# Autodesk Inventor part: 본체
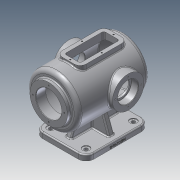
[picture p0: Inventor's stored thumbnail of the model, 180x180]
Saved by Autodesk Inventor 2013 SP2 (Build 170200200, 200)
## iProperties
Created: 2021-11
Part Number: 본체
Material: 알루미늄 6061
Document SubType Name: Modeling
Designer: aa
Density: 2.71 g/cm^3
Mass: 3552.31 g
Surface Area: 2411.25 cm^2
Volume: 1310.81 cm^3
Author: aa
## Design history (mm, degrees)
sketch "스케치1"
  geometry: L1 (0, 0)-(210, 0); L2 (0, 0)-(0, 47.5); L3 (0, 47.5)-(10, 47.5); L4 (10, 47.5)-(10, 65); L5 (10, 65)-(185.993, 65); A1 r 100 centre (110, 0) between (210, 0) and (185.993, 65); 1 further point
  constraints: 10 end point, 2 parallel, 2 perpendicular, 2 point on circle, 1 centre point, 1 coincident, 1 horizontal, 1 horizontal alignment
  dimensions: "d0" = 210 distance of L1.end L1.start; "d1" = 100 radius of A1; "d2" = 95 diameter of L3 L1; "d3" = 130 diameter of L5 L1; "d4" = 10 distance of L2.end L3.end
revolve "회전1" sketch "스케치1" stored, may be unused: angle "d8" = 90 deg
feature "쉘1" dims "d9" = 10
sketch "스케치16"
  geometry: C1 r 55 at (0, 0) reference; C2 r 37.5 at (0, 0) reference; C3 r 55 at (0, 0); C4 r 32.5 at (0, 0)
  constraints: 2 centre point, 2 coincident, 1 concentric
  dimensions: "d121" = 65 diameter of C4
extrude "돌출9" join sketch "스케치16" distance "d122" = 5; taper "d123" = 0 deg
sketch "스케치17"
  geometry: C1 r 32.5 at (0, 0) reference; C2 r 37.5 at (0, 0) reference; C3 r 32.5 at (0, 0)
  constraints: 1 centre point, 1 coincident
  dimensions: "d124" = 65 diameter of C3
extrude "돌출10" join sketch "스케치17" distance "d125" = 20; taper "d126" = 0 deg
node "작업 평면1"
sketch "스케치2"
  geometry: L1 (0, 47.5)-(0, -47.5) reference; L2 (-50, -30)-(-170, -30); L3 (-170, -30)-(-170, 30); L4 (-170, 30)-(-50, 30); L5 (-50, 30)-(-50, -30); 3 further points
  constraints: 8 end point, 2 midpoint, 2 parallel, 1 horizontal, 1 horizontal alignment, 1 perpendicular
  dimensions: "d11" = 120 distance of L3.end L4.end; "d12" = 60 distance of L2.end L3.end; "d13" = 50 distance of point (-50, 0) point (0, 0)
extrude "돌출1" join sketch "스케치2" stored distance "d14" = 25; taper "d15" = 0 deg
fillet "모깎기1" dims "d16" = 15
sketch "스케치3"
  geometry: L1 (65, 30)-(155, 30) reference; L2 (50, -15)-(50, 15) reference; L3 (155, -30)-(65, -30) reference; L4 (170, 15)-(170, -15) reference; L5 (160, 15)-(160, -15); L6 (155, -20)-(65, -20); L7 (60, -15)-(60, 15); L8 (65, 20)-(155, 20); A1 r 15 centre (155, 15) between (170, 15) and (155, 30) reference; A2 r 15 centre (65, 15) between (65, 30) and (50, 15) reference; A3 r 15 centre (65, -15) between (50, -15) and (65, -30) reference; A4 r 15 centre (155, -15) between (155, -30) and (170, -15) reference; A5 r 5 centre (155, 15) between (160, 15) and (155, 20); A6 r 5 centre (155, -15) between (155, -20) and (160, -15); A7 r 5 centre (65, -15) between (60, -15) and (65, -20); A8 r 5 centre (65, 15) between (65, 20) and (60, 15); 1 further point
  constraints: 8 end point, 8 point on circle, 4 centre point, 7 other
  dimensions: "d17" = 10 distance between parallel lines of L1 L8
extrude "돌출2" cut sketch "스케치3" stored distance "d18" = 25; taper "d19" = 0 deg
sketch "스케치4"
  geometry: L1 (65, 30)-(155, 30) reference; L2 (170, 15)-(170, -15) reference; L3 (55, 0)-(165, 0); L4 (110, 25)-(110, -25); 5 further points
  constraints: 5 midpoint, 4 end point, 3 vertical alignment, 2 horizontal alignment, 2 perpendicular
  dimensions: "d20" = 50 distance of L4.start L4.end; "d22" = 110 distance of L3.end L3.start
hole "구멍1" sketch "스케치4" at (55, 0), (110, 25), (110, -25), (165, 0) diameter "d23" = 3.242; stored, may be unused: countersink angle "d27" = 90 deg, drill point angle "d29" = 118 deg; dims "d24" = 9, "d25" = 4, "d26" = 2, "d28" = 11
node "작업 평면2"
sketch "스케치5"
  geometry: L1 (0, -47.5)-(0, 47.5) reference; L2 (0, 0)-(127, 0); C1 r 40 at (127, 0)
  constraints: 2 end point, 1 centre point, 1 coincident, 1 perpendicular
  dimensions: "d31" = 127 distance of L2.start L2.end; "d32" = 80 diameter of C1
extrude "돌출3" join sketch "스케치5" stored distance "d33" = 25; taper "d34" = 0 deg
sketch "스케치6"
  geometry: C1 r 40 at (0, 0) reference; 2 further points
  constraints: 1 coincident
hole "구멍2" sketch "스케치6" at (0, 0) diameter "d35" = 42; stored, may be unused: countersink angle "d39" = 90 deg, drill point angle "d41" = 118 deg; dims "d36" = 9, "d37" = 52, "d38" = 18, "d40" = 75
fillet "모깎기2" dims "d42" = 0.3
sketch "스케치7"
  geometry: C1 r 26 at (0, 0) reference; 5 further points
  constraints: 2 horizontal alignment, 2 vertical alignment
  dimensions: "d44" = 32.5 distance of C1.centre point (0, 32.5); "d45" = 32.5 distance of point (-32.5, 0) C1.centre; "d46" = 32.5 distance of C1.centre point (0, -32.5); "d47" = 32.5 distance of C1.centre point (32.5, 0)
hole "구멍3" sketch "스케치7" at (0, 32.5), (32.5, 0), (-32.5, 0), (0, -32.5) diameter "d48" = 3.242; stored, may be unused: countersink angle "d52" = 90 deg, drill point angle "d54" = 118 deg; dims "d49" = 11, "d50" = 52, "d51" = 18, "d53" = 13
sketch "스케치8"
  geometry: L1 (0, 0)-(0, 40); C1 r 47.5 at (0, 0) reference; 1 further point
  constraints: 2 end point, 1 coincident, 1 vertical
  dimensions: "d55" = 40 distance of L1.start L1.end
hole "구멍4" sketch "스케치8" at (0, 40) diameter "d56" = 3.242; stored, may be unused: countersink angle "d60" = 90 deg, drill point angle "d62" = 118 deg; dims "d57" = 11, "d58" = 52, "d59" = 18, "d61" = 13
node "작업 평면3"
sketch "스케치9"
  geometry: L1 (0, 47.5)-(0, -47.5) reference; L2 (0, 0)-(-30, 0); L3 (-30, -65)-(-190, -65); L4 (-190, -65)-(-190, 65); L5 (-190, 65)-(-30, 65); L6 (-30, 65)-(-30, -65)
  constraints: 10 end point, 2 parallel, 2 perpendicular, 1 horizontal, 1 midpoint
  dimensions: "d67" = 30 distance of L2.end L2.start; "d68" = 160 distance of L4.end L5.end; "d69" = 130 distance of L3.end L4.end
extrude "돌출4" join sketch "스케치9" distance "d70" = 14; taper "d71" = 0 deg
fillet "모깎기3" dims "d72" = 20
node "작업 평면4"
sketch "스케치14"
  geometry: L1 (170, -100)-(50, -100) reference; L2 (30, -100)-(50, -100) reference; L3 (170, -100)-(190, -100) reference; L4 (25, -55)-(181.239, -55) reference; L5 (50, -100)-(63.681, -62.412); L6 (10, -65)-(185.993, -65) reference; L7 (50, -100)-(170, -100); L8 (170, -100)-(156.319, -62.412); L9 (170, -100)-(210, -100); L10 (156.319, -62.412)-(63.681, -62.412); 1 further point
  constraints: 10 end point, 2 point on line, 1 equal length, 1 horizontal
  dimensions: "d98" = 110 deg angle of L2 L5; "d101" = 20 distance of L5.start L2.start; "d102" = 120 distance of L5.start L7.end; "d104" = 40 distance of L5.start L5.end; "d105" = 40 distance of L7.end L8.end; "d106" = 110 deg angle of L9 L8
extrude "돌출8" join sketch "스케치14" stored distance "d107" = 14; taper "d108" = 0 deg
sketch "스케치11"
  geometry: L1 (-100, 65)-(-100, 45) reference; L2 (-100, -45)-(-100, 45) reference; L3 (-55.515, 33.809)-(-100, 50); L4 (-100, 0)-(-100, 50); 2 further points
  constraints: 4 end point, 1 collinear, 1 midpoint, 1 point on line, 2 other
  dimensions: "d80" = 50 distance of L4.start L3.end; "d81" = 110 deg angle of L1 L3
feature "리브1" sketch "스케치11" dims "d82" = 1, "d83" = 14, "d84" = 0, "d85" = 0, "d86" = 1, "d87" = 1
fillet "모깎기4" dims "d96" = 3
fillet "모깎기5" dims "d97" = 3
fillet "모깎기6" dims "d109" = 10
fillet "모깎기7" dims "d110" = 3
chamfer "모따기1" distance "d111" = 1; stored, may be unused: second distance "d112" = 2, angle "d113" = 45 deg
sketch "스케치15"
  geometry: A1 r 17 centre (50, -45) between (33, -45) and (50, -62) reference; A2 r 17 centre (170, -45) between (170, -62) and (187, -45) reference; A3 r 17 centre (170, 45) between (187, 45) and (170, 62) reference; A4 r 17 centre (50, 45) between (50, 62) and (33, 45) reference; 5 further points
  constraints: 4 coincident
hole "구멍5" sketch "스케치15" at (50, 45), (170, 45), (170, -45), (50, -45) diameter "d114" = 9; stored, may be unused: countersink angle "d118" = 90 deg, drill point angle "d120" = 118 deg; dims "d115" = 11, "d116" = 18, "d117" = 2, "d119" = 13
sketch "스케치18"
  geometry: L1 (0, 0)-(120, 0) reference; 3 further points
  constraints: 1 midpoint, 1 vertical alignment, 1 other
  dimensions: "d127" = 5 distance of point (60, 0) point (60, 5)
feature "엠보싱1" sketch "스케치18" dims "d0" = 210, "d129" = 0.5, "d130" = 0
fillet "모깎기8" dims "d131" = 3
node "솔리드1"
mirror "대칭1"
pattern_circular "원형 패턴1" dims angle "d64" = 360 deg
mirror "대칭2"
other parameters: "d30" = 75, "d66" = -114
